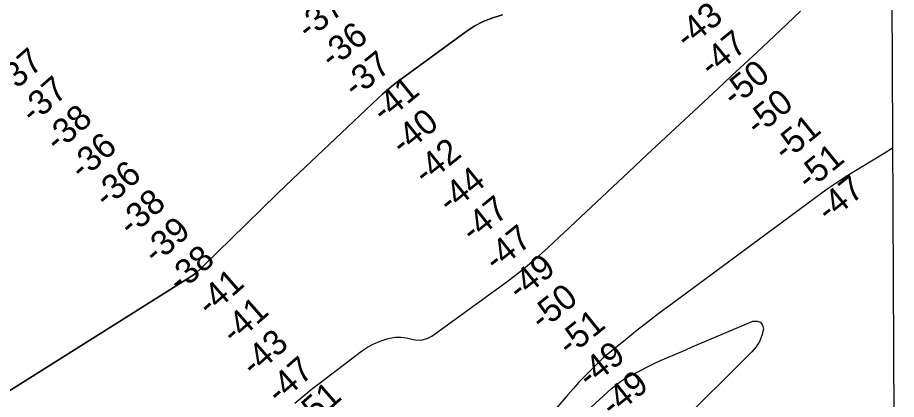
# Model space of a CAD drawing. Extents: x 3419139 to 3457078, y 540382 to 565875.
# Drawn here: x 3452566 to 3454925, y 547397 to 548420 of the extents above; entities that cross this region are included whole.
import ezdxf

# ---------------------------------------------------------------- set-up
doc = ezdxf.new("R2010")
doc.units = 0
for name, color, linetype in [('V-GRID-FRAM', 7, 'Continuous'), ('V-RIVR-RANG', 7, 'Continuous'), ('V-TOPO-DPTH', 7, 'Continuous'), ('V-TOPO-MAJR', 7, 'Continuous'), ('V-TOPO-MINR', 7, 'Continuous')]:
    doc.layers.add(name, color=color, linetype=linetype)

msp = doc.modelspace()

# ---------------------------------------------------------------- linework, layer by layer
at = {"layer": 'V-GRID-FRAM'}
msp.add_lwpolyline([(3423200.9, 563955.1), (3454837.9, 564093.1), (3454925.2, 545910.2), (3423272.3, 545772.1), (3423200.9, 563955.1)], dxfattribs=at)
at = {"layer": 'V-TOPO-DPTH'}
for points in [[(3453868.2, 548427.9), (3453841.8, 548420), (3453816.4, 548410.1), (3453792.3, 548397.2), (3453769.1, 548382.3), (3453583.5, 548246.2), (3453570.6, 548236.4), (3453558, 548226.2), (3453545.8, 548215.6), (3453533.9, 548204.7), (3453305.4, 547987.8), (3453263.4, 547947.7), (3453221.5, 547907.5), (3453179.9, 547867), (3453138.4, 547826.4), (3453070.2, 547759.2), (3453062.9, 547752.2), (3453055.4, 547745.2), (3453047.8, 547738.4), (3453040.1, 547731.8), (3452324.9, 547282.4)], [(3452324.9, 547282.4), (3453040.1, 547731.8), (3453047.8, 547738.4), (3453055.4, 547745.2), (3453062.9, 547752.2), (3453070.2, 547759.2), (3453138.4, 547826.4), (3453179.9, 547867), (3453221.5, 547907.5), (3453263.4, 547947.7), (3453305.4, 547987.8), (3453533.9, 548204.7), (3453545.8, 548215.6), (3453558, 548226.2), (3453570.6, 548236.4), (3453583.5, 548246.2), (3453769.1, 548382.3), (3453792.3, 548397.2), (3453816.4, 548410.1), (3453841.8, 548420), (3453868.2, 548427.9)]]:
    msp.add_lwpolyline(points, dxfattribs=at)
at = {"layer": 'V-TOPO-MAJR'}
for points in [[(3453310.2, 547387), (3453326.4, 547400.6), (3453342.7, 547414), (3453359.2, 547427.1), (3453375.9, 547440), (3453489.8, 547526.2), (3453505.7, 547536.8), (3453522.3, 547546), (3453539.8, 547553.2), (3453558.1, 547559.1), (3453565.9, 547561.1), (3453580.7, 547563.5), (3453595.3, 547564.2), (3453609.9, 547562.3), (3453624.5, 547558.8), (3453638.6, 547556.2), (3453652.3, 547556.3), (3453665.5, 547560.3), (3453678.2, 547566.9), (3453876.6, 547710.3), (3453906.2, 547732.6), (3453935.3, 547755.6), (3453963.4, 547779.7), (3453990.9, 547804.5), (3454206.8, 548006.6), (3454256.6, 548053.2), (3454306.4, 548099.8), (3454356.3, 548146.3), (3454406.1, 548192.8), (3454461.6, 548244.6), (3454483.7, 548265.2), (3454505.9, 548285.9), (3454528, 548306.5), (3454550.1, 548327.2), (3454614.1, 548386.9), (3454668.1, 548437.6)], [(3454914.8, 548070.1), (3454892.2, 548056.5), (3454790.5, 547994.3), (3454774.1, 547984), (3454757.9, 547973.3), (3454741.9, 547962.3), (3454726.1, 547951), (3454323.8, 547654.3), (3454291.8, 547630.4), (3454260.2, 547606.2), (3454228.8, 547581.6), (3454197.7, 547556.7), (3454142.3, 547511.7), (3454139.1, 547509), (3454135.9, 547506.3), (3454132.9, 547503.4), (3454129.9, 547500.6), (3454104.1, 547474.9), (3454088.5, 547459), (3454073.1, 547442.9), (3454058.1, 547426.4), (3454043.4, 547409.6), (3453701.3, 547011.6)], [(3453733.4, 547035.6), (3454159.6, 547425.3), (3454171.8, 547435.6), (3454184.6, 547445.2), (3454198.2, 547453.8), (3454212.2, 547461.5), (3454258.8, 547485), (3454275.4, 547493.1), (3454292.1, 547501), (3454308.9, 547508.6), (3454325.9, 547515.9), (3454342.9, 547523.1), (3454359.9, 547530.3), (3454376.9, 547537.5), (3454393.9, 547544.7), (3454539.9, 547606.8), (3454551.3, 547607.1), (3454560.2, 547604.2), (3454565.4, 547596.4), (3454568, 547585.2), (3454563.9, 547568.2), (3454557.8, 547552.2), (3454548.6, 547537.7), (3454537.5, 547524.2), (3454331.7, 547319.9)]]:
    msp.add_lwpolyline(points, dxfattribs=at)
at = {"layer": 'V-TOPO-MINR'}
msp.add_lwpolyline([(3453868.2, 548427.9), (3453841.8, 548420), (3453816.4, 548410.1), (3453792.3, 548397.2), (3453769.1, 548382.3), (3453583.5, 548246.2), (3453570.6, 548236.4), (3453558, 548226.2), (3453545.8, 548215.6), (3453533.9, 548204.7), (3453305.4, 547987.8), (3453263.4, 547947.7), (3453221.5, 547907.5), (3453179.9, 547867), (3453138.4, 547826.4), (3453070.2, 547759.2), (3453062.9, 547752.2), (3453055.4, 547745.2), (3453047.8, 547738.4), (3453040.1, 547731.8), (3452324.9, 547282.4)], dxfattribs=at)

# ---------------------------------------------------------------- texts
at = {"layer": 'V-RIVR-RANG'}
for s, rotation, p in [('-37', 38.8436, (3453347.6, 548358.7)), ('-43', 39.1152, (3454363.6, 548333.9)), ('-36', 38.8436, (3453410.3, 548280.8)), ('-47', 39.1152, (3454428.7, 548258)), ('-37', 41.2263, (3452542.4, 548208.5)), ('-37', 38.8436, (3453472.6, 548202.6)), ('-50', 39.1152, (3454489.6, 548178.6)), ('-37', 41.2263, (3452608.1, 548133.1)), ('-41', 38.8436, (3453549.1, 548135.8)), ('-50', 39.1152, (3454552.5, 548100.8)), ('-38', 41.2263, (3452673.7, 548057.6)), ('-40', 38.8436, (3453600.2, 548048.5)), ('-51', 39.1152, (3454626.9, 548032.4)), ('-36', 41.2263, (3452739.8, 547982.6)), ('-42', 38.8436, (3453661.3, 547969.3)), ('-51', 39.1152, (3454689.7, 547954.7)), ('-36', 41.2263, (3452805.5, 547907.2)), ('-44', 38.8436, (3453726, 547893.1)), ('-47', 39.1152, (3454743.2, 547869.3)), ('-38', 41.2263, (3452870.8, 547831.5)), ('-47', 38.8436, (3453788.2, 547814.7)), ('-39', 41.2263, (3452937.1, 547756.6)), ('-47', 38.8436, (3453850.7, 547736.7)), ('-38', 41.2263, (3453002.2, 547680.7)), ('-49', 38.8436, (3453913.6, 547659)), ('-41', 41.2263, (3453081.6, 547617.3)), ('-50', 38.8436, (3453973.7, 547579)), ('-41', 41.2263, (3453147.4, 547542)), ('-51', 38.8436, (3454047.7, 547510.2)), ('-43', 41.2263, (3453200.2, 547455.3)), ('-49', 38.8436, (3454101.2, 547424.9)), ('-47', 41.2263, (3453268.1, 547381.8)), ('-49', 38.8436, (3454163.7, 547346.8)), ('-51', 41.2263, (3453342.9, 547314.4))]:
    msp.add_text(s, height=67, rotation=rotation, dxfattribs=at).set_placement(p)

doc.saveas('drawing.dxf')
